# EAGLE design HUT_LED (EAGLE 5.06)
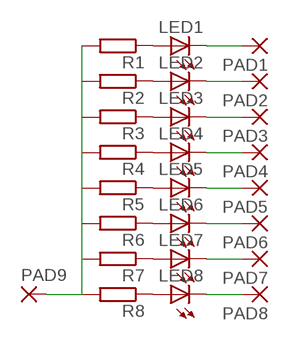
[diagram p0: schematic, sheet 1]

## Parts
LED1  LED3MM  [LED3MM]
LED2  LED3MM  [LED3MM]
LED3  LED3MM  [LED3MM]
LED4  LED3MM  [LED3MM]
LED5  LED3MM  [LED3MM]
LED6  LED3MM  [LED3MM]
LED7  LED3MM  [LED3MM]
LED8  LED3MM  [LED3MM]
PAD1  2,15/1,0  [2,15/1,0]
PAD2  2,15/1,0  [2,15/1,0]
PAD3  2,15/1,0  [2,15/1,0]
PAD4  2,15/1,0  [2,15/1,0]
PAD5  2,15/1,0  [2,15/1,0]
PAD6  2,15/1,0  [2,15/1,0]
PAD7  2,15/1,0  [2,15/1,0]
PAD8  2,15/1,0  [2,15/1,0]
PAD9  2,15/1,0  [2,15/1,0]
R1  R-EU_R0603  [R0603]
R2  R-EU_R0603  [R0603]
R3  R-EU_R0603  [R0603]
R4  R-EU_R0603  [R0603]
R5  R-EU_R0603  [R0603]
R6  R-EU_R0603  [R0603]
R7  R-EU_R0603  [R0603]
R8  R-EU_R0603  [R0603]

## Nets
N$1: LED1.A R1.1
N$2: LED2.A R2.1
N$3: LED3.A R3.1
N$4: LED4.A R4.1
N$5: LED5.A R5.1
N$6: LED6.A R6.1
N$7: LED7.A R7.1
N$8: LED8.A R8.1
N$9: PAD9.1(P) R1.2 R2.2 R3.2 R4.2 R5.2 R6.2 R7.2 R8.2
N$10: LED1.K(C) PAD1.1(P)
N$11: LED2.K(C) PAD2.1(P)
N$12: LED3.K(C) PAD3.1(P)
N$13: LED4.K(C) PAD4.1(P)
N$14: LED5.K(C) PAD5.1(P)
N$15: LED6.K(C) PAD6.1(P)
N$16: LED7.K(C) PAD7.1(P)
N$17: LED8.K(C) PAD8.1(P)

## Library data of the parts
LED1-LED8 = led:LED: LED
PAD1-PAD9 = wirepad:2,15/1,0: THROUGH-HOLE PAD
R1-R8 = rcl:R-EU_: RESISTOR, European symbol

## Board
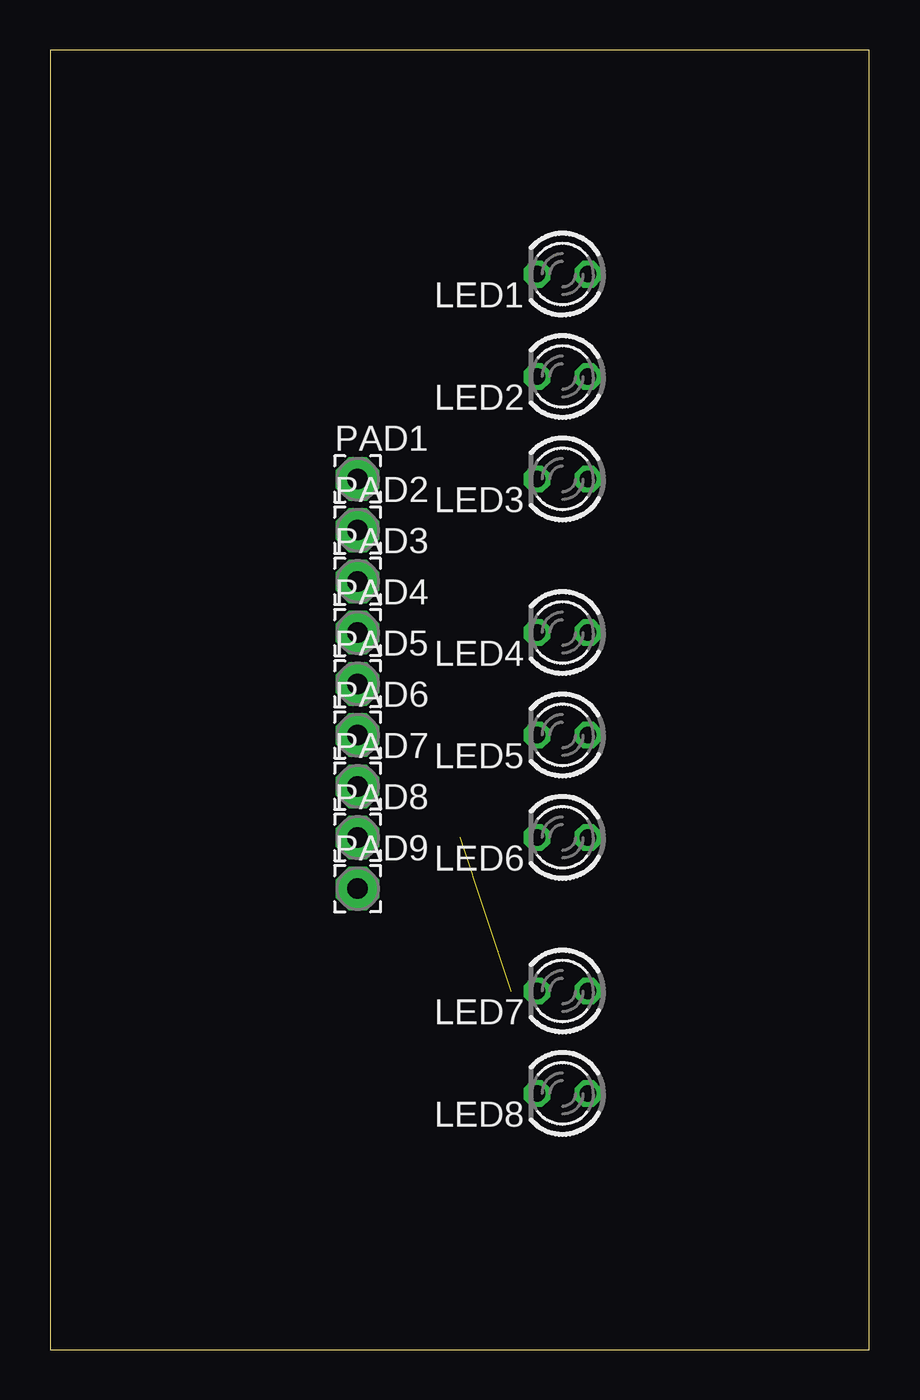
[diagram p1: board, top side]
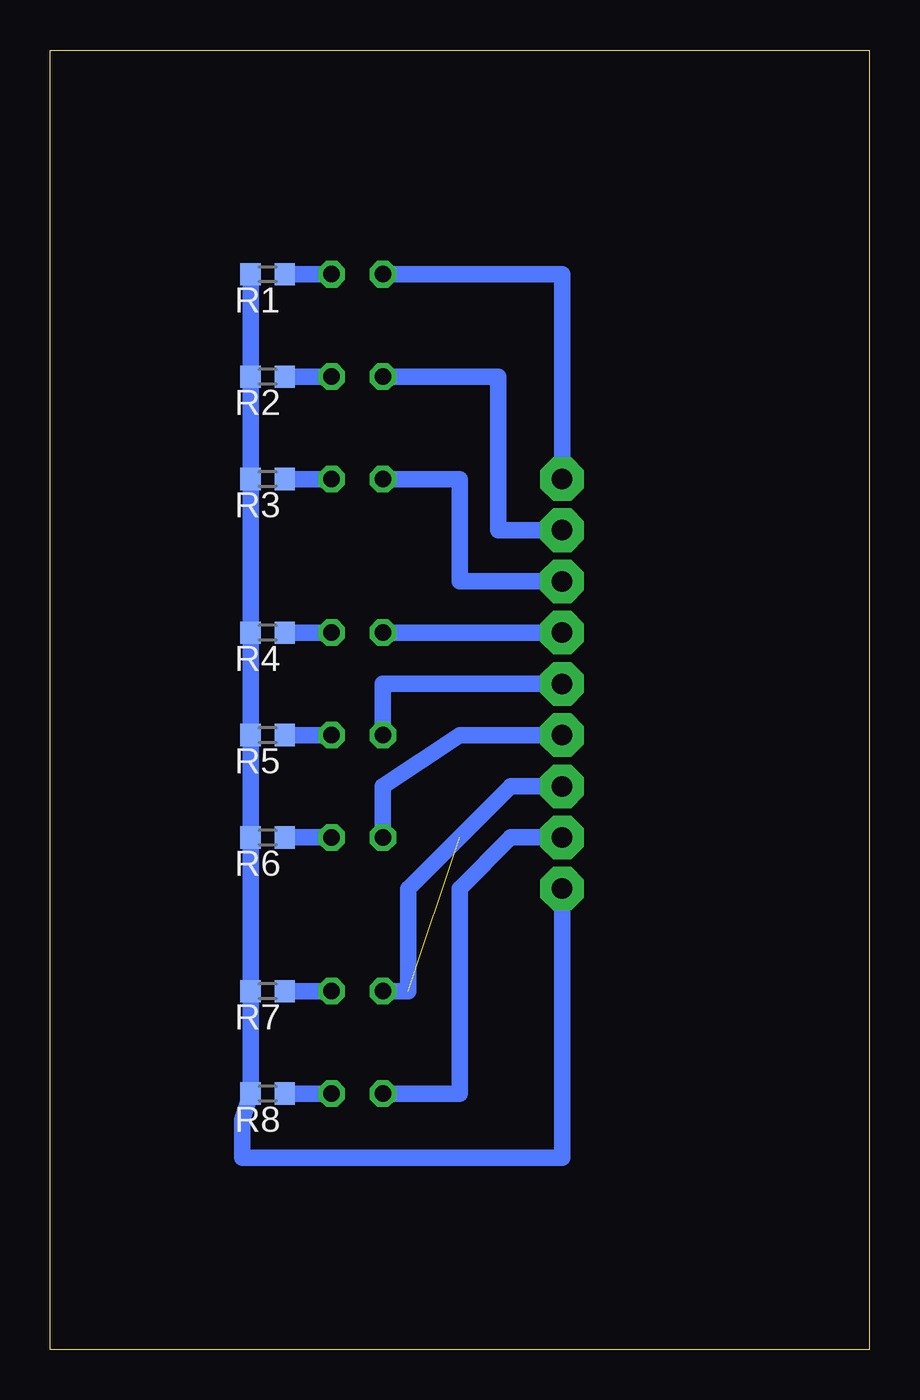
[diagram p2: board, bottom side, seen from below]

Size 40.62 x 64.44 mm. Coordinates in mm from the lower left corner, seen from the top.
Outline: 0,0 40.62,0 40.62,64.44 0,64.44 0,0
Copper layers (1*16): Top 0.035mm / dielectric 1.5mm / Bottom 0.035mm
Design rules "default": minimum track width 10mil, minimum drill 24mil, track to track 8mil, track to pad 8mil, pad to pad 8mil, via to via 8mil, smd to smd 8mil, copper to edge 40mil, drill to drill 8mil, minimum pad ring 10mil, minimum via ring 8mil, stop-mask expansion 4mil, vias tented up to drill 0mil, thermal gap 10mil

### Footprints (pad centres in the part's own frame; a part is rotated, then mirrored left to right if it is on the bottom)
LED3MM = drill 0.813 octagon: A -1.27,0; K 1.27,0
2,15/1,0 = drill 1.016 pad 2.159 octagon: 1 0,0
R0603 = smd 1 x 1.1: 1 -0.85,0; 2 0.85,0

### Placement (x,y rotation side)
LED1  25.4,53.34 180 top
LED2  25.4,48.26 180 top
LED3  25.4,43.18 180 top
LED4  25.4,35.56 180 top
LED5  25.4,30.48 180 top
LED6  25.4,25.4 180 top
LED7  25.4,17.78 180 top
LED8  25.4,12.7 180 top
PAD1  15.24,43.18 0 top
PAD2  15.24,40.64 0 top
PAD3  15.24,38.1 0 top
PAD4  15.24,35.56 0 top
PAD5  15.24,33.02 0 top
PAD6  15.24,30.48 0 top
PAD7  15.24,27.94 0 top
PAD8  15.24,25.4 0 top
PAD9  15.24,22.86 0 top
R1  29.84,53.34 180 bottom
R2  29.84,48.26 180 bottom
R3  29.84,43.18 180 bottom
R4  29.84,35.56 180 bottom
R5  29.84,30.48 180 bottom
R6  29.84,25.4 180 bottom
R7  29.84,17.78 180 bottom
R8  29.84,12.7 180 bottom

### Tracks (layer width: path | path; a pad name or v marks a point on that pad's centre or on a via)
N$1
  Bottom 0.813: LED1.A R1.1
N$2
  Bottom 0.813: LED2.A R2.1
N$3
  Bottom 0.813: LED3.A R3.1
N$4
  Bottom 0.813: LED4.A R4.1
N$5
  Bottom 0.813: LED5.A R5.1
N$6
  Bottom 0.813: LED6.A R6.1
N$7
  Bottom 0.813: LED7.A R7.1
N$8
  Bottom 0.813: LED8.A R8.1
N$9
  Bottom 0.813: PAD9.1 15.24,9.53 31.11,9.53 31.11,11.43 R8.2 R7.2 R6.2 R5.2 R4.2 R3.2 R2.2 R1.2
N$10
  Bottom 0.813: PAD1.1 15.24,53.34 LED1.K
N$11
  Bottom 0.813: PAD2.1 18.41,40.64 18.41,48.26 LED2.K
N$12
  Bottom 0.813: PAD3.1 20.32,38.1 20.32,43.18 LED3.K
N$13
  Bottom 0.813: PAD4.1 LED4.K
N$14
  Bottom 0.813: PAD5.1 24.13,33.02 LED5.K
N$15
  Bottom 0.813: PAD6.1 20.32,30.48 24.13,27.94 LED6.K
N$16  (1 unrouted)
  Bottom 0.813: PAD7.1 17.78,27.94 22.86,22.86 22.86,17.78 LED7.K
N$17
  Bottom 0.813: LED8.K 20.32,12.7 20.32,22.86 17.78,25.4 PAD8.1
